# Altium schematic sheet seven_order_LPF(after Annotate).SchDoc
size B
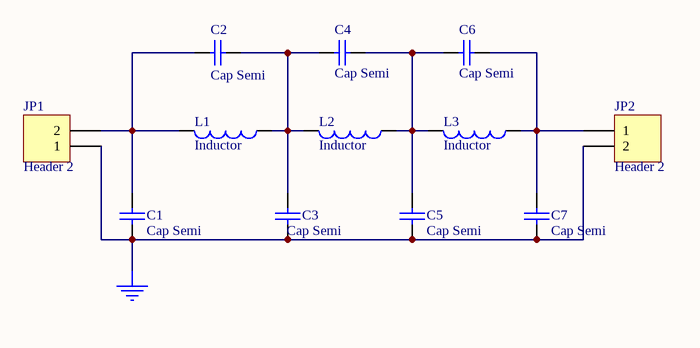
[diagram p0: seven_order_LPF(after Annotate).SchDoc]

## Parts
C1  Cap Semi  [C3216-1206]
C2  Cap Semi  [C3216-1206]
C3  Cap Semi  [C3216-1206]
C4  Cap Semi  [C3216-1206]
C5  Cap Semi  [C3216-1206]
C6  Cap Semi  [C3216-1206]
C7  Cap Semi  [C3216-1206]
JP1  Header 2  [HDR1X2]
JP2  Header 2  [HDR1X2]
L1  Inductor  [C1005-0402]
L2  Inductor  [C1005-0402]
L3  Inductor  [C1005-0402]

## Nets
GND: C1.2 C3.2 C5.2 C7.2 JP1.1 JP2.2
NetC1_1: C1.1 C2.1 JP1.2 L1.2
NetC2_2: C2.2 C3.1 C4.1 L1.1 L2.2
NetC4_2: C4.2 C5.1 C6.1 L2.1 L3.2
NetC6_2: C6.2 C7.1 JP2.1 L3.1

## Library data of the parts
C1-C7 = Cap Semi: Capacitor (Semiconductor SIM Model); Manufacturer: Generic Components; Class I: Passive; Value: 100pF
JP1 JP2 = Header 2: Header, 2-Pin; Manufacturer: Generic Components; Class I: Connector
L1-L3 = Inductor: Manufacturer: Generic Components; Class I: Passive; Value: 10mH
